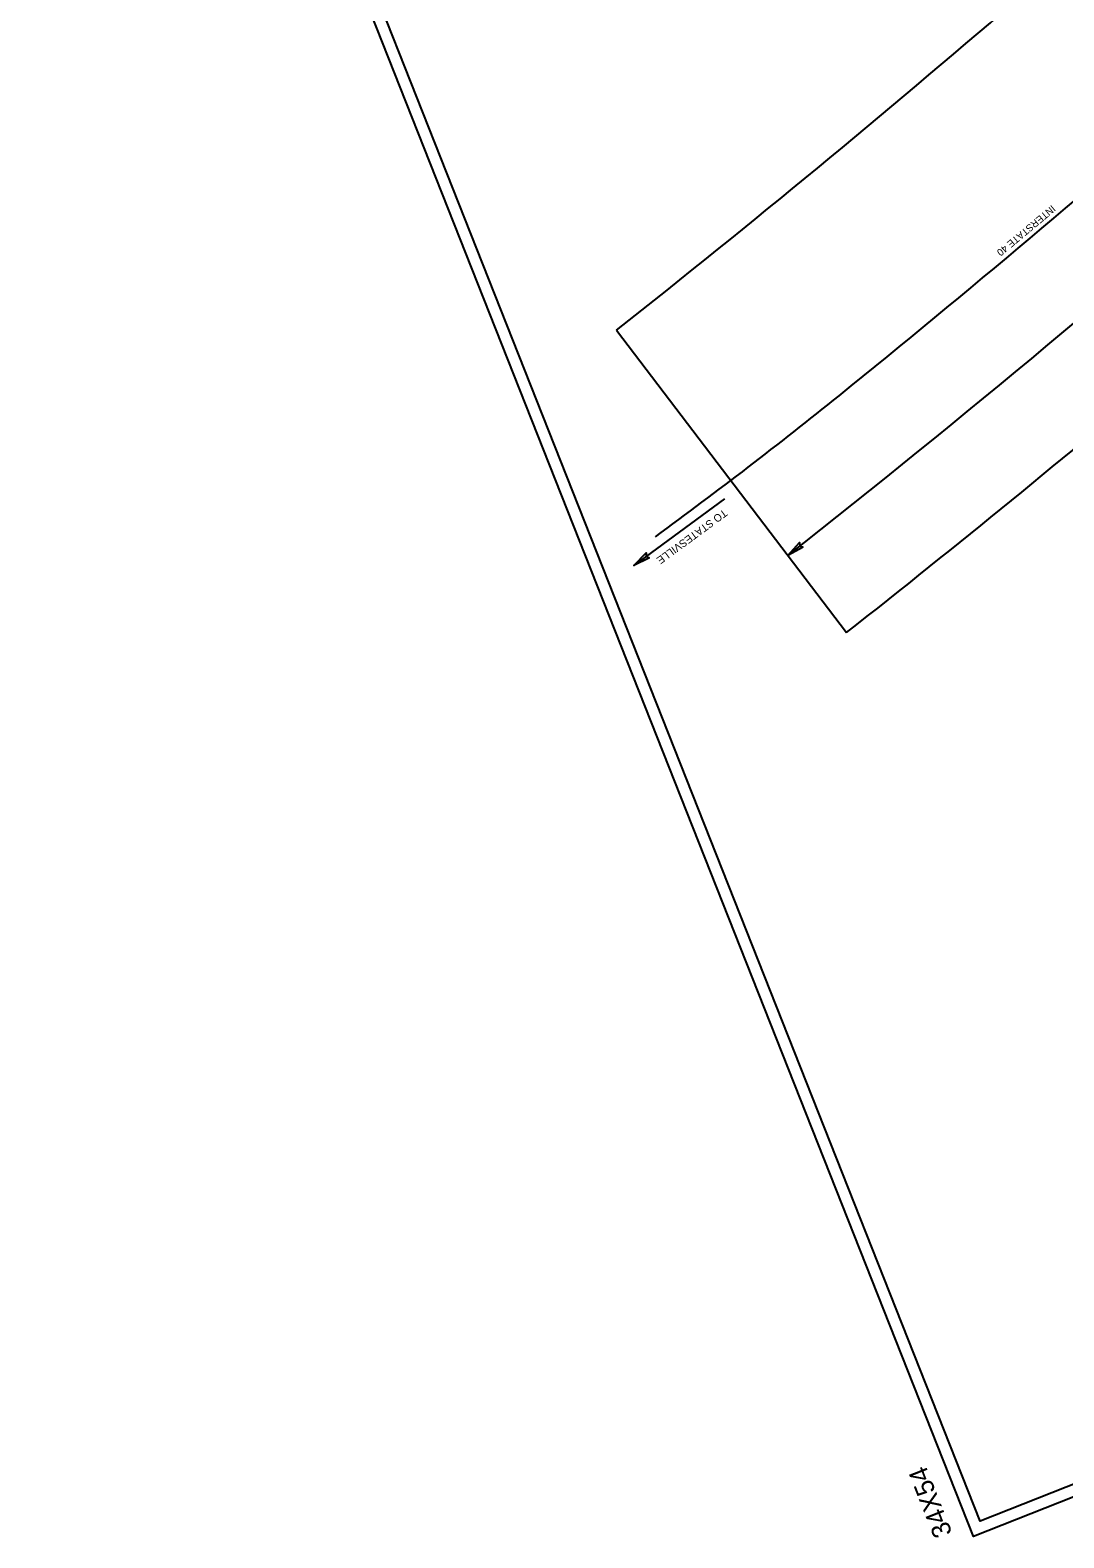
# Model space of a CAD drawing. Extents: x 1550555 to 1553129, y 809174 to 812311.
# Drawn here: x 1550555 to 1551643, y 809174 to 810761 of the extents above; entities that cross this region are included whole.
import ezdxf

# ---------------------------------------------------------------- set-up
doc = ezdxf.new("R2010")
doc.units = 0
for name, color, linetype in [('Old_Level_1', 7, 'Continuous'), ('P_RDY_Dimension', 7, 'Continuous'), ('P_RDY_Dimension_Text', 7, 'Continuous'), ('P_RDY_Terminator_Cell', 7, 'Continuous'), ('Pattern_4', 7, 'Continuous'), ('Site_Temp_Construction', 7, 'Continuous')]:
    doc.layers.add(name, color=color, linetype=linetype)

msp = doc.modelspace()

# ---------------------------------------------------------------- linework, layer by layer
at = {"layer": 'Old_Level_1'}
for points in [[(1552136.2, 812311.3), (1553129.1, 809800.4), (1551548.3, 809175.3), (1550555.4, 811686.1)], [(1552129.2, 812295), (1553112.9, 809807.5), (1551555.3, 809191.5), (1550571.6, 811679.1)]]:
    msp.add_lwpolyline(points, close=True, dxfattribs=at)
at = {"layer": 'P_RDY_Dimension'}
msp.add_arc((1543473.3, 820207.4), 12730.9, 308.23925, 311.40768, dxfattribs=at)
at = {"layer": 'P_RDY_Terminator_Cell'}
for points in [[(1551369.1, 810216.9), (1551353, 810208.2), (1551365.2, 810221.9), (1551365.4, 810218)], [(1551207.2, 810205.8), (1551190.9, 810197.6), (1551203.6, 810210.9), (1551203.6, 810207)]]:
    msp.add_lwpolyline(points, close=True, dxfattribs=at)
at = {"layer": 'Pattern_4'}
for centre, radius, start, end in [((1543473.3, 820207.4), 12632.8, 308.90318, 313.63201), ((1548259.3, 814276.7), 5011.9, 306.1171, 308.9032)]:
    msp.add_arc(centre, radius, start, end, dxfattribs=at)
at = {"layer": 'Site_Temp_Construction'}
for p, q in [((1551172.6, 810445.4), (1551414.7, 810127)), ((1551286.4, 810267.7), (1551190.9, 810197.6))]:
    msp.add_line(p, q, dxfattribs=at)
for radius, start, end in [(12432.8, 308.26298, 310.76768), (12832.8, 308.23138, 310.21774)]:
    msp.add_arc((1543473.3, 820207.4), radius, start, end, dxfattribs=at)

# ---------------------------------------------------------------- texts
at = {"layer": 'P_RDY_Dimension_Text'}
for s, height, rotation, p in [('INTERSTATE 40', 7.5, 219.9238, (1551630.7, 810577.5)), ('TO STATESVILLE', 8, 216.2614, (1551285.4, 810257.4))]:
    msp.add_text(s, height=height, rotation=rotation, dxfattribs=at).set_placement(p)
at = {"layer": 'Site_Temp_Construction'}
msp.add_text('34X54', height=20, rotation=111.5761, dxfattribs=at).set_placement((1551526.3, 809179))

doc.saveas('drawing.dxf')
